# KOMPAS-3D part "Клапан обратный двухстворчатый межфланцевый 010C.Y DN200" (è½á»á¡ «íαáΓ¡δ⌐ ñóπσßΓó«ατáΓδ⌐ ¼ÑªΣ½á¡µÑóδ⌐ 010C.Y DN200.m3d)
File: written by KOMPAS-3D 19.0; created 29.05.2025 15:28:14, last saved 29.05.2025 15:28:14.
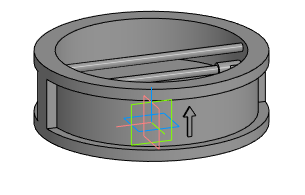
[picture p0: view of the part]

Document properties: Полное имя файла: E:\Dendor Работа Сачек\3D для проекитирвщиков\5.2 Тип 010C, 010C.Y Клапан обратный двухстворчатый межфланцевый\stp_Клапан обратный двухстворчатый межфланцевый 010C.Y\Клапан обратный двухстворчатый межфланцевый 010C.Y DN200.m3d

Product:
- Part/product: Клапан обратный двухстворчатый межфланцевый 010C.Y DN200

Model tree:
1. Операция без истории:1  (labels: Клапан обратный двухстворчатый межфланцевый 010C.Y DN200)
